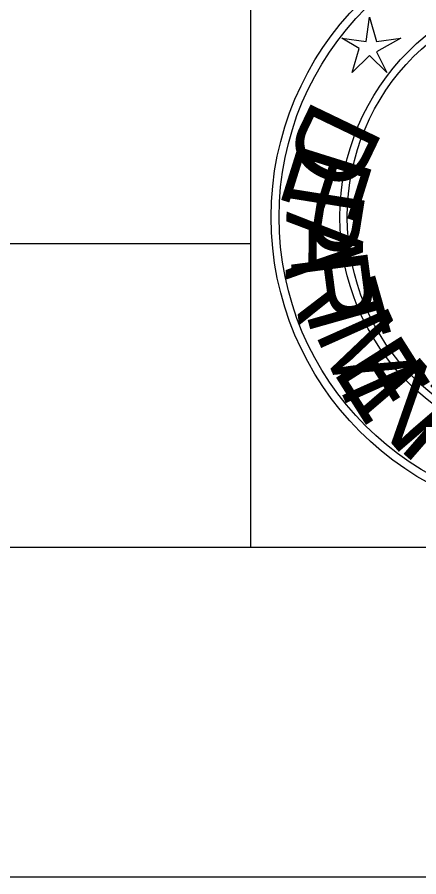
# Model space of a CAD drawing. Extents: x 1797809 to 2198143, y 249608 to 1237864.
# Drawn here: x 2195380.86 to 2195386.96, y 1237118.04 to 1237131.08 of the extents above; entities that cross this region are included whole.
import ezdxf

# ---------------------------------------------------------------- set-up
doc = ezdxf.new("R2010")
doc.units = 0
for name, color, linetype in [('GSBWFILL', 7, 'Continuous'), ('GSCOLORFILL', 7, 'Continuous'), ('GSSHT', 7, 'Continuous')]:
    doc.layers.add(name, color=color, linetype=linetype)

msp = doc.modelspace()

# ---------------------------------------------------------------- linework, layer by layer
at = {"layer": 'GSBWFILL'}
msp.add_lwpolyline([(2195386.216, 1237131.077), (2195386.321, 1237130.71), (2195386.689, 1237130.762), (2195386.321, 1237130.552), (2195386.479, 1237130.237), (2195386.216, 1237130.499), (2195385.953, 1237130.237), (2195386.058, 1237130.604), (2195385.796, 1237130.762), (2195386.164, 1237130.71)], close=True, dxfattribs=at)
msp.add_lwpolyline([(2195386.216, 1237131.077), (2195386.321, 1237130.71), (2195386.689, 1237130.762), (2195386.321, 1237130.552), (2195386.479, 1237130.237), (2195386.216, 1237130.499), (2195385.953, 1237130.237), (2195386.058, 1237130.604), (2195385.796, 1237130.762), (2195386.164, 1237130.71)], close=True, dxfattribs=at)
msp.add_lwpolyline([(2195386.216, 1237131.077), (2195386.321, 1237130.71), (2195386.689, 1237130.762), (2195386.321, 1237130.552), (2195386.479, 1237130.237), (2195386.216, 1237130.499), (2195385.953, 1237130.237), (2195386.058, 1237130.604), (2195385.796, 1237130.762), (2195386.164, 1237130.71)], close=True, dxfattribs=at)
for radius in [4.599, 4.599, 4.599, 4.478, 4.478, 4.478, 3.556, 3.556, 3.556, 3.444, 3.444, 3.444]:
    msp.add_circle((2195389.32, 1237128.045), radius, dxfattribs=at)
at = {"layer": 'GSCOLORFILL'}
for p, q in [((2195384.411, 1237123.036), (2195384.411, 1237133.046)), ((2195228.783, 1237127.646), (2195384.411, 1237127.646))]:
    msp.add_line(p, q, dxfattribs=at)
msp.add_lwpolyline([(2195216.286, 1237123.036), (2195538.786, 1237123.036), (2195538.786, 1237333.036), (2195216.286, 1237333.036)], close=True, dxfattribs=at)
at = {"layer": 'GSSHT'}
msp.add_lwpolyline([(2195203.786, 1237118.036), (2195543.786, 1237118.036), (2195543.786, 1237338.036), (2195203.786, 1237338.036)], close=True, dxfattribs=at)

# ---------------------------------------------------------------- texts
at = {"layer": 'GSBWFILL'}
for s, rotation, p in [('D', 244.3352, (2195385.375, 1237129.869)), ('D', 244.3352, (2195385.375, 1237129.869)), ('D', 244.3352, (2195385.375, 1237129.869)), ('E', 252.6236, (2195385.165, 1237129.238)), ('E', 252.6236, (2195385.165, 1237129.238)), ('E', 252.6236, (2195385.165, 1237129.238)), ('P', 260.912, (2195385.007, 1237128.607)), ('P', 260.912, (2195385.007, 1237128.607)), ('P', 260.912, (2195385.007, 1237128.607)), ('A', 269.2004, (2195384.955, 1237128.134)), ('A', 269.2004, (2195384.955, 1237128.134)), ('A', 269.2004, (2195384.955, 1237128.134)), ('R', 277.4888, (2195385.007, 1237127.451)), ('R', 277.4888, (2195385.007, 1237127.451)), ('R', 277.4888, (2195385.007, 1237127.451)), ('T', 285.7771, (2195385.165, 1237126.873)), ('T', 285.7771, (2195385.165, 1237126.873)), ('T', 285.7771, (2195385.165, 1237126.873)), ('M', 294.0655, (2195385.375, 1237126.295)), ('M', 294.0655, (2195385.375, 1237126.295)), ('M', 294.0655, (2195385.375, 1237126.295)), ('E', 302.3539, (2195385.638, 1237125.717)), ('E', 302.3539, (2195385.638, 1237125.717)), ('E', 302.3539, (2195385.638, 1237125.717)), ('N', 310.6423, (2195386.006, 1237125.244)), ('N', 310.6423, (2195386.006, 1237125.244)), ('N', 310.6423, (2195386.006, 1237125.244)), ('T', 318.9307, (2195386.426, 1237124.719)), ('T', 318.9307, (2195386.426, 1237124.719)), ('T', 318.9307, (2195386.426, 1237124.719))]:
    msp.add_text(s, height=1.17, rotation=rotation, dxfattribs=at).set_placement(p)

doc.saveas('drawing.dxf')
